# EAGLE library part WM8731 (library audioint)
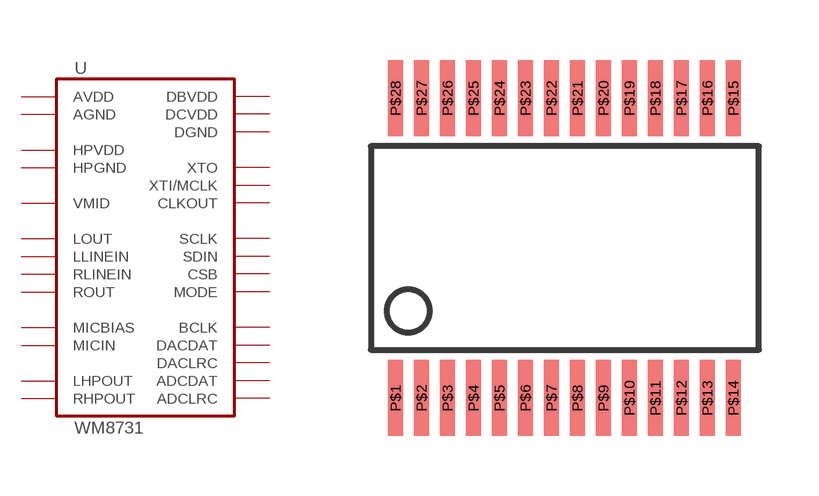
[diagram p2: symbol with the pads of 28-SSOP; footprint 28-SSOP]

Designator prefix -

## WM8731  [28-SSOP]
P$1  DBVDD  pwr
P$2  CLKOUT  out
P$3  BCLK
P$4  DACDAT  in
P$5  DACLRC
P$6  ADCDAT  out
P$7  ADCLRC
P$8  HPVDD  pwr
P$9  LHPOUT  out
P$10  RHPOUT  out
P$11  HPGND  pwr
P$12  LOUT  out
P$13  ROUT  out
P$14  AVDD  pwr
P$15  AGND  pwr
P$16  VMID  out
P$17  MICBIAS  out
P$18  MICIN  in
P$19  RLINEIN  in
P$20  LLINEIN  in
P$21  MODE  in
P$22  CSB  in
P$23  SDIN
P$24  SCLK  in
P$25  XTI/MCLK  in
P$26  XTO  out
P$27  DCVDD  pwr
P$28  DGND  pwr

## Footprint 28-SSOP (pad centres in mm)
smd 0.381 x 1.905: P$1 -4.55,-3.752; P$2 -3.9,-3.752; P$3 -3.25,-3.752; P$4 -2.6,-3.752; P$5 -1.95,-3.752; P$6 -1.3,-3.752; P$7 -0.65,-3.752; P$8 0,-3.752; P$9 0.65,-3.752; P$10 1.3,-3.752; P$11 1.95,-3.752; P$12 2.6,-3.752; P$13 3.25,-3.752; P$14 3.9,-3.752; P$15 3.9,3.752; P$16 3.25,3.752; P$17 2.6,3.752; P$18 1.95,3.752; P$19 1.3,3.752; P$20 0.65,3.752; P$21 0,3.752; P$22 -0.65,3.752; P$23 -1.3,3.752; P$24 -1.95,3.752; P$25 -2.6,3.752; P$26 -3.25,3.752; P$27 -3.9,3.752; P$28 -4.55,3.752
